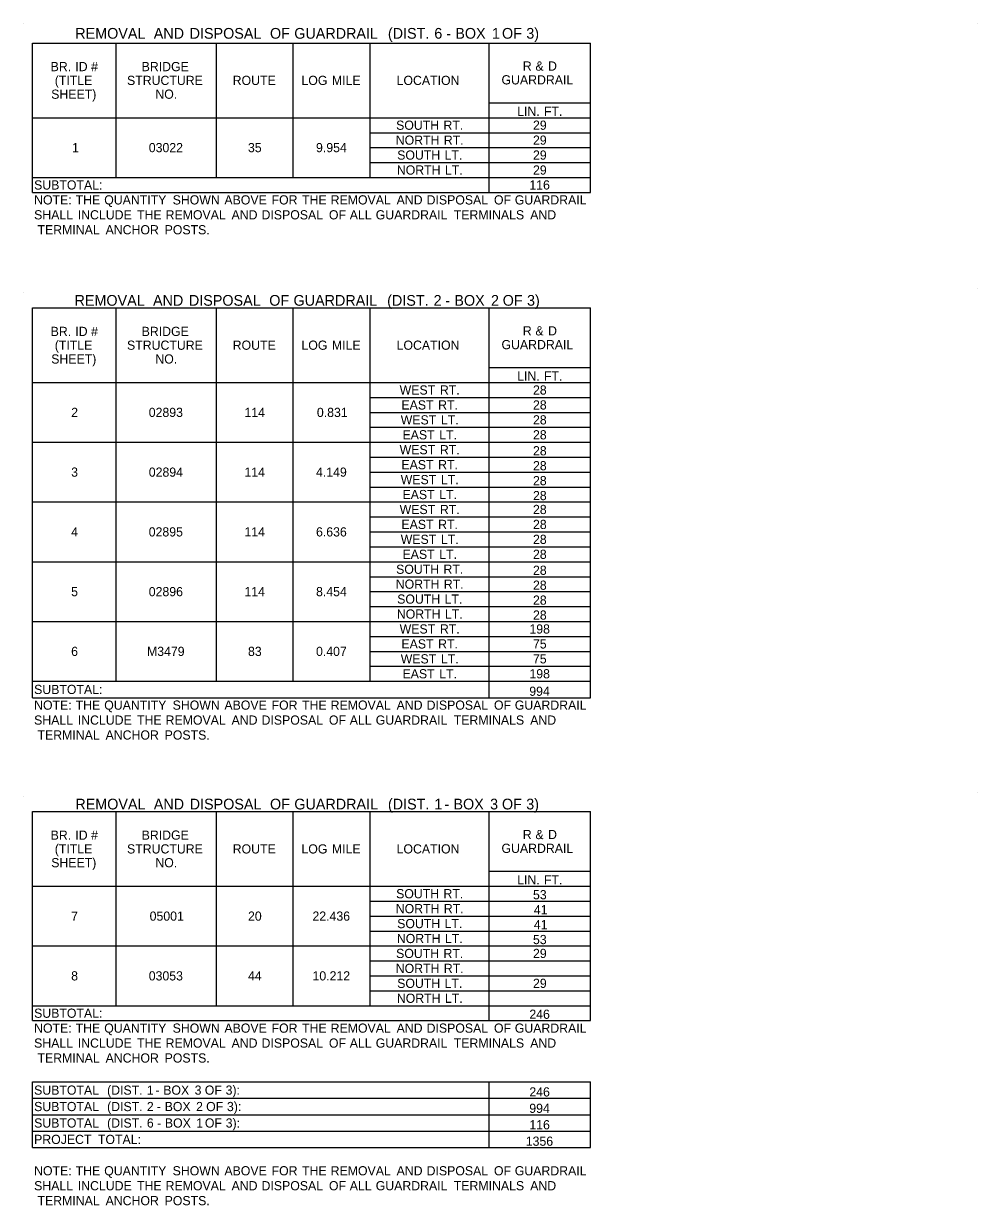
# Model space of a CAD drawing. Extents: x 542596 to 1930787, y -1948294 to 596640.
# Drawn here: x 546171 to 546793, y -1946949 to -1946178 of the extents above; entities that cross this region are included whole.
import ezdxf

# ---------------------------------------------------------------- set-up
doc = ezdxf.new("R2010")
doc.units = 0
doc.layers.add('Default', color=7, linetype='Continuous')

msp = doc.modelspace()

# ---------------------------------------------------------------- linework, layer by layer
at = {"layer": 'Default'}
for p, q in [((546170.57, -1946177.72), (546170.57, -1946177.72)), ((546792.95, -1946177.72), (546792.95, -1946177.72)), ((546176.42, -1946190.4), (546540.58, -1946190.4)), ((546176.42, -1946287.9), (546176.42, -1946190.4)), ((546176.42, -1946287.9), (546176.42, -1946190.4)), ((546231.02, -1946278.15), (546231.02, -1946190.4)), ((546296.35, -1946278.15), (546296.35, -1946190.4)), ((546346.56, -1946278.15), (546346.56, -1946190.4)), ((546396.77, -1946278.15), (546396.77, -1946190.4)), ((546474.28, -1946287.9), (546474.28, -1946190.4)), ((546540.58, -1946287.9), (546540.58, -1946190.4)), ((546474.28, -1946229.4), (546540.58, -1946229.4)), ((546176.42, -1946239.15), (546540.58, -1946239.15)), ((546231.02, -1946239.15), (546396.77, -1946239.15)), ((546396.77, -1946239.15), (546474.28, -1946239.15)), ((546474.28, -1946239.15), (546540.58, -1946239.15)), ((546396.77, -1946248.9), (546540.58, -1946248.9)), ((546396.77, -1946258.65), (546540.58, -1946258.65)), ((546396.77, -1946268.4), (546540.58, -1946268.4)), ((546176.42, -1946278.15), (546540.58, -1946278.15)), ((546396.77, -1946278.15), (546474.28, -1946278.15)), ((546474.28, -1946278.15), (546540.58, -1946278.15)), ((546176.42, -1946287.9), (546540.58, -1946287.9)), ((546792.95, -1946350.57), (546792.95, -1946350.57)), ((546170.57, -1946353.49), (546170.57, -1946353.49)), ((546176.42, -1946363.24), (546540.58, -1946363.24)), ((546176.42, -1946617.72), (546176.42, -1946363.24)), ((546176.42, -1946617.72), (546176.42, -1946363.24)), ((546231.02, -1946606.99), (546231.02, -1946363.24)), ((546296.35, -1946606.99), (546296.35, -1946363.24)), ((546346.56, -1946606.99), (546346.56, -1946363.24)), ((546396.77, -1946606.99), (546396.77, -1946363.24)), ((546474.28, -1946617.72), (546474.28, -1946363.24)), ((546540.58, -1946606.99), (546540.58, -1946363.24)), ((546474.28, -1946402.24), (546540.58, -1946402.24)), ((546176.42, -1946411.99), (546540.58, -1946411.99)), ((546396.77, -1946421.74), (546540.58, -1946421.74)), ((546396.77, -1946431.49), (546540.58, -1946431.49)), ((546396.77, -1946441.24), (546540.58, -1946441.24)), ((546176.42, -1946450.99), (546540.58, -1946450.99)), ((546396.77, -1946450.99), (546474.28, -1946450.99)), ((546474.28, -1946450.99), (546540.58, -1946450.99)), ((546396.77, -1946460.74), (546540.58, -1946460.74)), ((546396.77, -1946470.49), (546540.58, -1946470.49)), ((546396.77, -1946480.24), (546540.58, -1946480.24)), ((546176.42, -1946489.99), (546540.58, -1946489.99)), ((546396.77, -1946489.99), (546474.28, -1946489.99)), ((546474.28, -1946489.99), (546540.58, -1946489.99)), ((546396.77, -1946499.74), (546540.58, -1946499.74)), ((546396.77, -1946509.49), (546540.58, -1946509.49)), ((546396.77, -1946519.24), (546540.58, -1946519.24)), ((546176.42, -1946528.99), (546540.58, -1946528.99)), ((546396.77, -1946528.99), (546474.28, -1946528.99)), ((546474.28, -1946528.99), (546540.58, -1946528.99)), ((546396.77, -1946538.74), (546540.58, -1946538.74)), ((546396.77, -1946548.49), (546540.58, -1946548.49)), ((546396.77, -1946558.24), (546540.58, -1946558.24)), ((546176.42, -1946567.99), (546540.58, -1946567.99)), ((546396.77, -1946567.99), (546474.28, -1946567.99)), ((546474.28, -1946567.99), (546540.58, -1946567.99)), ((546396.77, -1946577.74), (546540.58, -1946577.74)), ((546396.77, -1946587.49), (546540.58, -1946587.49)), ((546396.77, -1946597.24), (546540.58, -1946597.24)), ((546176.42, -1946606.99), (546474.28, -1946606.99)), ((546396.77, -1946606.99), (546474.28, -1946606.99)), ((546474.28, -1946606.99), (546540.58, -1946606.99)), ((546474.28, -1946617.72), (546474.28, -1946606.99)), ((546540.58, -1946617.72), (546540.58, -1946606.99)), ((546176.42, -1946617.72), (546540.58, -1946617.72)), ((546170.57, -1946682.31), (546170.57, -1946682.31)), ((546792.95, -1946679.38), (546792.95, -1946679.38)), ((546176.42, -1946692.06), (546540.58, -1946692.06)), ((546176.42, -1946828.56), (546176.42, -1946692.06)), ((546176.42, -1946828.56), (546176.42, -1946692.06)), ((546231.02, -1946818.81), (546231.02, -1946692.06)), ((546296.35, -1946818.81), (546296.35, -1946692.06)), ((546346.56, -1946818.81), (546346.56, -1946692.06)), ((546396.77, -1946818.81), (546396.77, -1946692.06)), ((546474.28, -1946828.56), (546474.28, -1946692.06)), ((546540.58, -1946828.56), (546540.58, -1946692.06)), ((546474.28, -1946731.06), (546540.58, -1946731.06)), ((546176.42, -1946740.81), (546540.58, -1946740.81)), ((546176.42, -1946740.81), (546540.58, -1946740.81)), ((546396.77, -1946750.56), (546540.58, -1946750.56)), ((546396.77, -1946760.31), (546540.58, -1946760.31)), ((546396.77, -1946770.06), (546540.58, -1946770.06)), ((546176.42, -1946779.81), (546540.58, -1946779.81)), ((546396.77, -1946779.81), (546474.28, -1946779.81)), ((546474.28, -1946779.81), (546540.58, -1946779.81)), ((546396.77, -1946789.56), (546540.58, -1946789.56)), ((546396.77, -1946799.31), (546540.58, -1946799.31)), ((546396.77, -1946809.06), (546540.58, -1946809.06)), ((546176.42, -1946818.81), (546540.58, -1946818.81)), ((546396.77, -1946818.81), (546474.28, -1946818.81)), ((546474.28, -1946818.81), (546540.58, -1946818.81)), ((546176.42, -1946828.56), (546540.58, -1946828.56)), ((546176.42, -1946868.53), (546540.58, -1946868.53)), ((546176.42, -1946868.53), (546540.58, -1946868.53)), ((546176.42, -1946911.43), (546176.42, -1946868.53)), ((546176.42, -1946911.43), (546176.42, -1946868.53)), ((546474.28, -1946911.43), (546474.28, -1946868.53)), ((546474.28, -1946911.43), (546474.28, -1946868.53)), ((546540.58, -1946911.43), (546540.58, -1946868.53)), ((546176.42, -1946879.26), (546540.58, -1946879.26)), ((546176.42, -1946889.98), (546540.58, -1946889.98)), ((546176.42, -1946900.71), (546540.58, -1946900.71)), ((546176.42, -1946911.43), (546540.58, -1946911.43))]:
    msp.add_line(p, q, dxfattribs=at)

# ---------------------------------------------------------------- texts
for s, height, p in [('REMOVAL', 7, (546204.26, -1946187.56)), (' AND', 7, (546252.88, -1946187.56)), (' DISPOSAL', 7, (546276.3, -1946187.56)), (' OF', 7, (546328.72, -1946187.56)), (' GUARDRAIL', 7, (546344.57, -1946187.56)), (' (DIST.', 7, (546405.68, -1946187.56)), (' 6', 7, (546435.97, -1946187.56)), (' BOX', 7, (546449.68, -1946187.56)), (' 1', 7, (546473.58, -1946187.56)), (' OF', 7, (546480.15, -1946187.56)), (' 3)', 7, (546495.99, -1946187.56)), (' -', 7, (546443.78, -1946187.56)), ('BR.', 6, (546188.2, -1946208.77)), (' ID', 6, (546202.06, -1946208.77)), (' #', 6, (546212.35, -1946208.77)), ('BRIDGE', 6, (546247.59, -1946208.77)), ('R', 6, (546496.32, -1946208.4)), (' &', 6, (546502.33, -1946208.4)), (' D', 6, (546510.58, -1946208.4)), ('(TITLE', 6, (546190.89, -1946217.77)), ('STRUCTURE', 6, (546238.04, -1946217.77)), ('ROUTE', 6, (546306.99, -1946217.77)), ('LOG', 6, (546351.87, -1946217.77)), (' MILE', 6, (546369.52, -1946217.77)), ('LOCATION', 6, (546413.97, -1946217.77)), ('GUARDRAIL', 6, (546482.41, -1946217.4)), ('SHEET)', 6, (546188.57, -1946226.77)), ('NO.', 6, (546256.52, -1946226.77)), ('LIN.', 6, (546492.64, -1946237.95)), (' FT.', 6, (546507.9, -1946237.95)), ('SOUTH', 6, (546413.64, -1946247.02)), (' RT.', 6, (546442.31, -1946247.02)), ('29', 6, (546502.96, -1946247.02)), ('NORTH', 6, (546413.41, -1946256.77)), (' RT.', 6, (546442.54, -1946256.77)), ('29', 6, (546502.96, -1946256.77)), ('1', 6, (546202.16, -1946261.65)), ('03022', 6, (546252.25, -1946261.65)), ('35', 6, (546316.96, -1946261.65)), ('9.954', 6, (546361.38, -1946261.65)), ('SOUTH', 6, (546414.34, -1946266.52)), (' LT.', 6, (546443.01, -1946266.52)), ('29', 6, (546502.96, -1946266.52)), ('NORTH', 6, (546414.11, -1946276.27)), (' LT.', 6, (546443.24, -1946276.27)), ('29', 6, (546502.96, -1946276.27)), ('SUBTOTAL:', 6, (546177.4, -1946286.02)), ('116', 6, (546500.59, -1946286.02)), ('NOTE:', 6, (546177.4, -1946295.77)), (' THE', 6, (546202.28, -1946295.77)), (' QUANTITY', 6, (546220.93, -1946295.77)), (' SHOWN', 6, (546265.58, -1946295.77)), (' ABOVE', 6, (546299.36, -1946295.77)), (' FOR', 6, (546330.14, -1946295.77)), (' THE', 6, (546350.05, -1946295.77)), (' REMOVAL', 6, (546368.7, -1946295.77)), (' AND', 6, (546411.73, -1946295.77)), (' DISPOSAL', 6, (546431.31, -1946295.77)), (' OF', 6, (546475.27, -1946295.77)), (' GUARDRAIL', 6, (546488.86, -1946295.77)), ('SHALL', 6, (546177.4, -1946305.52)), (' INCLUDE', 6, (546203.66, -1946305.52)), (' THE', 6, (546242.34, -1946305.52)), (' REMOVAL', 6, (546260.99, -1946305.52)), (' AND', 6, (546304.02, -1946305.52)), (' DISPOSAL', 6, (546323.6, -1946305.52)), (' OF', 6, (546367.57, -1946305.52)), (' ALL', 6, (546381.15, -1946305.52)), (' GUARDRAIL', 6, (546398.1, -1946305.52)), (' TERMINALS', 6, (546449.04, -1946305.52)), (' AND', 6, (546498.91, -1946305.52)), (' TERMINAL', 6, (546177.4, -1946315.27)), (' ANCHOR', 6, (546221.82, -1946315.27)), (' POSTS.', 6, (546260.36, -1946315.27)), ('REMOVAL', 7, (546203.79, -1946361.87)), (' AND', 7, (546252.4, -1946361.87)), (' DISPOSAL', 7, (546275.82, -1946361.87)), (' OF', 7, (546328.25, -1946361.87)), (' GUARDRAIL', 7, (546344.1, -1946361.87)), (' (DIST.', 7, (546405.2, -1946361.87)), (' 2', 7, (546435.5, -1946361.87)), (' -', 7, (546443.16, -1946361.87)), (' BOX', 7, (546449.06, -1946361.87)), (' 2', 7, (546472.96, -1946361.87)), (' OF', 7, (546480.62, -1946361.87)), (' 3)', 7, (546496.47, -1946361.87)), ('BR.', 6, (546188.2, -1946381.62)), (' ID', 6, (546202.06, -1946381.62)), (' #', 6, (546212.35, -1946381.62)), ('BRIDGE', 6, (546247.59, -1946381.62)), ('R', 6, (546496.32, -1946381.24)), (' &', 6, (546502.33, -1946381.24)), (' D', 6, (546510.58, -1946381.24)), ('(TITLE', 6, (546190.89, -1946390.62)), ('STRUCTURE', 6, (546238.04, -1946390.62)), ('ROUTE', 6, (546306.99, -1946390.62)), ('LOG', 6, (546351.87, -1946390.62)), (' MILE', 6, (546369.52, -1946390.62)), ('LOCATION', 6, (546413.97, -1946390.62)), ('GUARDRAIL', 6, (546482.41, -1946390.24)), ('SHEET)', 6, (546188.57, -1946399.62)), ('NO.', 6, (546256.52, -1946399.62)), ('LIN.', 6, (546492.64, -1946410.79)), (' FT.', 6, (546507.9, -1946410.79)), ('WEST', 6, (546415.95, -1946419.87)), (' RT.', 6, (546440, -1946419.87)), ('28', 6, (546502.96, -1946419.87)), ('2', 6, (546201.61, -1946434.49)), ('02893', 6, (546252.22, -1946434.49)), ('114', 6, (546314.67, -1946434.49)), ('0.831', 6, (546361.95, -1946434.49)), ('EAST', 6, (546417.11, -1946429.62)), (' RT.', 6, (546438.84, -1946429.62)), ('28', 6, (546502.96, -1946429.62)), ('WEST', 6, (546416.65, -1946439.37)), (' LT.', 6, (546440.7, -1946439.37)), ('28', 6, (546502.96, -1946439.37)), ('EAST', 6, (546417.81, -1946449.12)), (' LT.', 6, (546439.54, -1946449.12)), ('28', 6, (546502.96, -1946449.12)), ('WEST', 6, (546415.95, -1946458.87)), (' RT.', 6, (546440, -1946458.87)), ('28', 6, (546502.96, -1946459.54)), ('EAST', 6, (546417.11, -1946468.62)), (' RT.', 6, (546438.84, -1946468.62)), ('28', 6, (546502.96, -1946469.29)), ('3', 6, (546201.58, -1946473.49)), ('02894', 6, (546252.24, -1946473.49)), ('114', 6, (546314.67, -1946473.49)), ('4.149', 6, (546361.37, -1946473.49)), ('WEST', 6, (546416.65, -1946478.37)), (' LT.', 6, (546440.7, -1946478.37)), ('28', 6, (546502.96, -1946479.04)), ('EAST', 6, (546417.81, -1946488.12)), (' LT.', 6, (546439.54, -1946488.12)), ('28', 6, (546502.96, -1946488.79)), ('WEST', 6, (546415.95, -1946497.87)), (' RT.', 6, (546440, -1946497.87)), ('28', 6, (546502.96, -1946497.87)), ('EAST', 6, (546417.11, -1946507.62)), (' RT.', 6, (546438.84, -1946507.62)), ('28', 6, (546502.96, -1946507.62)), ('4', 6, (546201.59, -1946512.49)), ('02895', 6, (546252.2, -1946512.49)), ('114', 6, (546314.67, -1946512.49)), ('6.636', 6, (546361.37, -1946512.49)), ('WEST', 6, (546416.65, -1946517.37)), (' LT.', 6, (546440.7, -1946517.37)), ('28', 6, (546502.96, -1946517.37)), ('EAST', 6, (546417.81, -1946527.12)), (' LT.', 6, (546439.54, -1946527.12)), ('28', 6, (546502.96, -1946527.12)), ('SOUTH', 6, (546413.64, -1946536.87)), (' RT.', 6, (546442.31, -1946536.87)), ('28', 6, (546502.96, -1946537.54)), ('NORTH', 6, (546413.41, -1946546.62)), (' RT.', 6, (546442.54, -1946546.62)), ('28', 6, (546502.96, -1946547.29)), ('5', 6, (546201.56, -1946551.49)), ('02896', 6, (546252.22, -1946551.49)), ('114', 6, (546314.67, -1946551.49)), ('8.454', 6, (546361.38, -1946551.49)), ('SOUTH', 6, (546414.34, -1946556.37)), (' LT.', 6, (546443.01, -1946556.37)), ('28', 6, (546502.96, -1946557.04)), ('NORTH', 6, (546414.11, -1946566.12)), (' LT.', 6, (546443.24, -1946566.12)), ('28', 6, (546502.96, -1946566.79)), ('WEST', 6, (546415.95, -1946575.87)), (' RT.', 6, (546440, -1946575.87)), ('198', 6, (546500.63, -1946575.87)), ('EAST', 6, (546417.11, -1946585.62)), (' RT.', 6, (546438.84, -1946585.62)), ('75', 6, (546502.94, -1946585.62)), ('6', 6, (546201.58, -1946590.49)), ('M3479', 6, (546251.06, -1946590.49)), ('83', 6, (546316.98, -1946590.49)), ('0.407', 6, (546361.37, -1946590.49)), ('WEST', 6, (546416.65, -1946595.37)), (' LT.', 6, (546440.7, -1946595.37)), ('75', 6, (546502.94, -1946595.37)), ('EAST', 6, (546417.81, -1946605.12)), (' LT.', 6, (546439.54, -1946605.12)), ('198', 6, (546500.63, -1946605.12)), ('SUBTOTAL:', 6, (546177.4, -1946615.35)), ('994', 6, (546500.54, -1946616.52)), ('NOTE:', 6, (546177.4, -1946625.59)), (' THE', 6, (546202.28, -1946625.59)), (' QUANTITY', 6, (546220.93, -1946625.59)), (' SHOWN', 6, (546265.58, -1946625.59)), (' ABOVE', 6, (546299.36, -1946625.59)), (' FOR', 6, (546330.14, -1946625.59)), (' THE', 6, (546350.05, -1946625.59)), (' REMOVAL', 6, (546368.7, -1946625.59)), (' AND', 6, (546411.73, -1946625.59)), (' DISPOSAL', 6, (546431.31, -1946625.59)), (' OF', 6, (546475.27, -1946625.59)), (' GUARDRAIL', 6, (546488.86, -1946625.59)), ('SHALL', 6, (546177.4, -1946635.34)), (' INCLUDE', 6, (546203.66, -1946635.34)), (' REMOVAL', 6, (546260.99, -1946635.34)), (' DISPOSAL', 6, (546323.6, -1946635.34)), (' OF', 6, (546367.57, -1946635.34)), (' GUARDRAIL', 6, (546398.1, -1946635.34)), (' TERMINALS', 6, (546449.04, -1946635.34)), (' THE', 6, (546242.34, -1946635.34)), (' AND', 6, (546304.02, -1946635.34)), (' ALL', 6, (546381.15, -1946635.34)), (' AND', 6, (546498.91, -1946635.34)), (' TERMINAL', 6, (546177.4, -1946645.09)), (' ANCHOR', 6, (546221.82, -1946645.09)), (' POSTS.', 6, (546260.36, -1946645.09)), ('REMOVAL', 7, (546204.3, -1946690.68)), (' AND', 7, (546252.91, -1946690.68)), (' DISPOSAL', 7, (546276.34, -1946690.68)), (' OF', 7, (546328.76, -1946690.68)), (' GUARDRAIL', 7, (546344.61, -1946690.68)), (' (DIST.', 7, (546405.71, -1946690.68)), (' 1', 7, (546436.01, -1946690.68)), (' -', 7, (546442.58, -1946690.68)), (' BOX', 7, (546448.48, -1946690.68)), (' 3', 7, (546472.38, -1946690.68)), (' OF', 7, (546480.11, -1946690.68)), (' 3)', 7, (546495.96, -1946690.68)), ('BR.', 6, (546188.2, -1946710.43)), (' ID', 6, (546202.06, -1946710.43)), (' #', 6, (546212.35, -1946710.43)), ('BRIDGE', 6, (546247.59, -1946710.43)), ('R', 6, (546496.32, -1946710.06)), (' &', 6, (546502.33, -1946710.06)), (' D', 6, (546510.58, -1946710.06)), ('(TITLE', 6, (546190.89, -1946719.43)), ('STRUCTURE', 6, (546238.04, -1946719.43)), ('ROUTE', 6, (546306.99, -1946719.43)), ('LOG', 6, (546351.87, -1946719.43)), (' MILE', 6, (546369.52, -1946719.43)), ('LOCATION', 6, (546413.97, -1946719.43)), ('GUARDRAIL', 6, (546482.41, -1946719.06)), ('SHEET)', 6, (546188.57, -1946728.43)), ('NO.', 6, (546256.52, -1946728.43)), ('LIN.', 6, (546492.64, -1946739.61)), (' FT.', 6, (546507.9, -1946739.61)), ('SOUTH', 6, (546413.64, -1946748.68)), (' RT.', 6, (546442.31, -1946748.68)), ('53', 6, (546502.96, -1946749.36)), ('NORTH', 6, (546413.41, -1946758.43)), (' RT.', 6, (546442.54, -1946758.43)), ('7', 6, (546201.58, -1946763.31)), ('05001', 6, (546252.8, -1946763.31)), ('20', 6, (546316.99, -1946763.31)), ('22.436', 6, (546359.04, -1946763.31)), ('41', 6, (546503.54, -1946759.11)), ('SOUTH', 6, (546414.34, -1946768.18)), (' LT.', 6, (546443.01, -1946768.18)), ('41', 6, (546503.54, -1946768.86)), ('NORTH', 6, (546414.11, -1946777.93)), (' LT.', 6, (546443.24, -1946777.93)), ('53', 6, (546502.96, -1946778.61)), ('SOUTH', 6, (546413.64, -1946787.68)), (' RT.', 6, (546442.31, -1946787.68)), ('29', 6, (546502.96, -1946787.68)), ('8', 6, (546201.58, -1946802.31)), ('03053', 6, (546252.22, -1946802.31)), ('44', 6, (546317, -1946802.31)), ('10.212', 6, (546359.07, -1946802.31)), ('NORTH', 6, (546413.41, -1946797.43)), (' RT.', 6, (546442.54, -1946797.43)), ('SOUTH', 6, (546414.34, -1946807.18)), (' LT.', 6, (546443.01, -1946807.18)), ('29', 6, (546502.96, -1946807.18)), ('NORTH', 6, (546414.11, -1946816.93)), (' LT.', 6, (546443.24, -1946816.93)), ('SUBTOTAL:', 6, (546177.4, -1946826.68)), ('246', 6, (546500.59, -1946827.36)), ('NOTE:', 6, (546177.4, -1946836.43)), (' THE', 6, (546202.28, -1946836.43)), (' QUANTITY', 6, (546220.93, -1946836.43)), (' SHOWN', 6, (546265.58, -1946836.43)), (' ABOVE', 6, (546299.36, -1946836.43)), (' FOR', 6, (546330.14, -1946836.43)), (' THE', 6, (546350.05, -1946836.43)), (' REMOVAL', 6, (546368.7, -1946836.43)), (' AND', 6, (546411.73, -1946836.43)), (' DISPOSAL', 6, (546431.31, -1946836.43)), (' OF', 6, (546475.27, -1946836.43)), (' GUARDRAIL', 6, (546488.86, -1946836.43)), ('SHALL', 6, (546177.4, -1946846.18)), (' INCLUDE', 6, (546203.66, -1946846.18)), (' THE', 6, (546242.34, -1946846.18)), (' REMOVAL', 6, (546260.99, -1946846.18)), (' AND', 6, (546304.02, -1946846.18)), (' DISPOSAL', 6, (546323.6, -1946846.18)), (' OF', 6, (546367.57, -1946846.18)), (' ALL', 6, (546381.15, -1946846.18)), (' GUARDRAIL', 6, (546398.1, -1946846.18)), (' TERMINALS', 6, (546449.04, -1946846.18)), (' AND', 6, (546498.91, -1946846.18)), (' TERMINAL', 6, (546177.4, -1946855.93)), (' ANCHOR', 6, (546221.82, -1946855.93)), (' POSTS.', 6, (546260.36, -1946855.93)), ('SUBTOTAL', 6, (546177.4, -1946876.9)), (' (DIST.', 6, (546222.79, -1946876.9)), (' 1', 6, (546248.76, -1946876.9)), (' -', 6, (546254.39, -1946876.9)), (' BOX', 6, (546259.44, -1946876.9)), (' 3', 6, (546279.93, -1946876.9)), (' OF', 6, (546286.56, -1946876.9)), (' 3):', 6, (546300.14, -1946876.9)), ('246', 6, (546500.59, -1946878.06)), ('SUBTOTAL', 6, (546177.4, -1946887.62)), (' (DIST.', 6, (546222.79, -1946887.62)), (' 2', 6, (546248.76, -1946887.62)), (' BOX', 6, (546260.38, -1946887.62)), (' 2', 6, (546280.87, -1946887.62)), (' OF', 6, (546287.44, -1946887.62)), (' 3):', 6, (546301.02, -1946887.62)), ('994', 6, (546500.54, -1946888.78)), (' -', 6, (546255.32, -1946887.62)), ('SUBTOTAL', 6, (546177.4, -1946898.35)), (' (DIST.', 6, (546222.79, -1946898.35)), (' 6', 6, (546248.76, -1946898.35)), (' -', 6, (546255.45, -1946898.35)), (' BOX', 6, (546260.5, -1946898.35)), (' 1', 6, (546280.99, -1946898.35)), (' OF', 6, (546286.62, -1946898.35)), (' 3):', 6, (546300.2, -1946898.35)), ('116', 6, (546500.59, -1946899.51)), ('PROJECT', 6, (546177.4, -1946909.07)), (' TOTAL:', 6, (546216.82, -1946909.07)), ('1356', 6, (546498.26, -1946910.23)), ('NOTE:', 6, (546177.4, -1946929.55)), (' THE', 6, (546202.28, -1946929.55)), (' QUANTITY', 6, (546220.93, -1946929.55)), (' SHOWN', 6, (546265.58, -1946929.55)), (' ABOVE', 6, (546299.36, -1946929.55)), (' FOR', 6, (546330.14, -1946929.55)), (' THE', 6, (546350.05, -1946929.55)), (' REMOVAL', 6, (546368.7, -1946929.55)), (' AND', 6, (546411.73, -1946929.55)), (' DISPOSAL', 6, (546431.31, -1946929.55)), (' OF', 6, (546475.27, -1946929.55)), (' GUARDRAIL', 6, (546488.86, -1946929.55)), ('SHALL', 6, (546177.4, -1946939.3)), (' INCLUDE', 6, (546203.66, -1946939.3)), (' THE', 6, (546242.34, -1946939.3)), (' REMOVAL', 6, (546260.99, -1946939.3)), (' AND', 6, (546304.02, -1946939.3)), (' DISPOSAL', 6, (546323.6, -1946939.3)), (' OF', 6, (546367.57, -1946939.3)), (' ALL', 6, (546381.15, -1946939.3)), (' GUARDRAIL', 6, (546398.1, -1946939.3)), (' TERMINALS', 6, (546449.04, -1946939.3)), (' AND', 6, (546498.91, -1946939.3)), (' TERMINAL', 6, (546177.4, -1946949.05)), (' ANCHOR', 6, (546221.82, -1946949.05)), (' POSTS.', 6, (546260.36, -1946949.05))]:
    msp.add_text(s, height=height, dxfattribs=at).set_placement(p)

doc.saveas('drawing.dxf')
